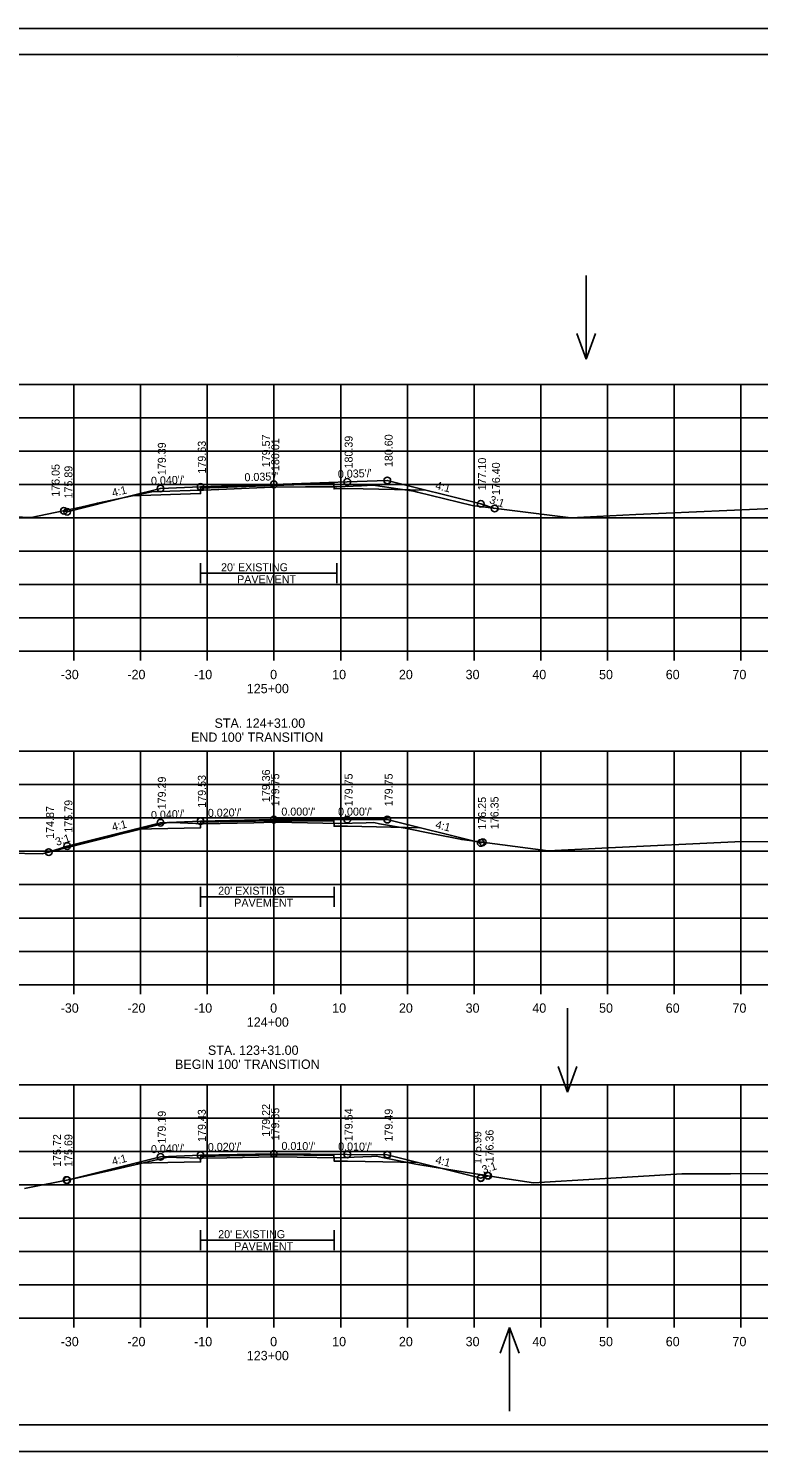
# Model space of a CAD drawing. Extents: x 915787 to 919910, y 133456 to 136717.
# Drawn here: x 916377.2 to 916486.6, y 136229.4 to 136442.8 of the extents above; entities that cross this region are included whole.
import ezdxf

# ---------------------------------------------------------------- set-up
doc = ezdxf.new("R2010")
doc.units = 0
for name, color, linetype in [('R_Axis', 7, 'Continuous'), ('R_Axis Annot', 7, 'Continuous'), ('R_Border', 7, 'Continuous'), ('R_Border Notes', 7, 'Continuous'), ('R_Exist Surface', 7, 'Continuous'), ('R_Exist Surface Annot', 7, 'Continuous'), ('R_Fin Surface', 7, 'Continuous'), ('R_Grid', 7, 'Continuous'), ('R_No Plot', 7, 'Continuous'), ('R_Water Annot', 7, 'Continuous'), ('R_Xsect Elev', 7, 'Continuous'), ('R_Xsect Slope', 7, 'Continuous')]:
    doc.layers.add(name, color=color, linetype=linetype)

msp = doc.modelspace()

# ---------------------------------------------------------------- linework, layer by layer
at = {"layer": 'R_Axis'}
for p, q in [((916273.98, 136349.41), (916553.98, 136349.41)), ((916383.98, 136348.01), (916383.98, 136349.41)), ((916393.98, 136348.01), (916393.98, 136349.41)), ((916403.98, 136348.01), (916403.98, 136349.41)), ((916413.98, 136348.01), (916413.98, 136349.41)), ((916423.98, 136348.01), (916423.98, 136349.41)), ((916433.98, 136348.01), (916433.98, 136349.41)), ((916443.98, 136348.01), (916443.98, 136349.41)), ((916453.98, 136348.01), (916453.98, 136349.41)), ((916463.98, 136348.01), (916463.98, 136349.41)), ((916473.98, 136348.01), (916473.98, 136349.41)), ((916483.98, 136348.01), (916483.98, 136349.41)), ((916273.98, 136299.41), (916553.98, 136299.41)), ((916383.98, 136298.01), (916383.98, 136299.41)), ((916393.98, 136298.01), (916393.98, 136299.41)), ((916403.98, 136298.01), (916403.98, 136299.41)), ((916413.98, 136298.01), (916413.98, 136299.41)), ((916423.98, 136298.01), (916423.98, 136299.41)), ((916433.98, 136298.01), (916433.98, 136299.41)), ((916443.98, 136298.01), (916443.98, 136299.41)), ((916453.98, 136298.01), (916453.98, 136299.41)), ((916463.98, 136298.01), (916463.98, 136299.41)), ((916473.98, 136298.01), (916473.98, 136299.41)), ((916483.98, 136298.01), (916483.98, 136299.41)), ((916273.98, 136249.41), (916553.98, 136249.41)), ((916383.98, 136248.01), (916383.98, 136249.41)), ((916393.98, 136248.01), (916393.98, 136249.41)), ((916403.98, 136248.01), (916403.98, 136249.41)), ((916413.98, 136248.01), (916413.98, 136249.41)), ((916423.98, 136248.01), (916423.98, 136249.41)), ((916433.98, 136248.01), (916433.98, 136249.41)), ((916443.98, 136248.01), (916443.98, 136249.41)), ((916453.98, 136248.01), (916453.98, 136249.41)), ((916463.98, 136248.01), (916463.98, 136249.41)), ((916473.98, 136248.01), (916473.98, 136249.41)), ((916483.98, 136248.01), (916483.98, 136249.41))]:
    msp.add_line(p, q, dxfattribs=at)
at = {"layer": 'R_Border'}
for p, q in [((916255.98, 136438.87), (916572.16, 136438.87)), ((916408.5, 136438.61), (916408.5, 136438.61)), ((916408.5, 136438.61), (916408.5, 136438.61)), ((916572.16, 136233.41), (916255.98, 136233.41))]:
    msp.add_line(p, q, dxfattribs=at)
at = {"layer": 'R_Exist Surface'}
for points in [[(916367.17, 136369.83), (916377.58, 136369.43), (916385.03, 136371), (916387.51, 136371.62), (916394.69, 136373.08), (916395.67, 136373.29), (916396.84, 136373.33), (916402.95, 136373.54), (916403.4, 136373.56), (916413.72, 136373.98), (916418.73, 136374.03), (916423.4, 136374.03), (916427.12, 136374.2), (916428.83, 136374.3), (916434.26, 136373.48), (916434.95, 136373.38), (916435.5, 136373.25), (916443.69, 136371.25), (916446.48, 136370.88), (916458.49, 136369.38), (916468.2, 136369.88), (916490.97, 136370.92)], [(916374.01, 136319.15), (916379.22, 136319.03), (916389.03, 136321.49), (916390.35, 136321.83), (916393.19, 136322.53), (916398.06, 136323.73), (916399.94, 136323.68), (916403.42, 136323.55), (916410.95, 136323.7), (916413.94, 136323.77), (916416.64, 136323.72), (916423.64, 136323.57), (916427.79, 136323.68), (916428.93, 136323.71), (916429.82, 136323.55), (916433.66, 136322.88), (916437.82, 136322.02), (916442.12, 136321.17), (916450.11, 136320.13), (916455.09, 136319.5), (916464.13, 136319.93), (916483.04, 136320.82), (916497.05, 136320.95)], [(916376.61, 136268.88), (916384.15, 136270.37), (916389.69, 136271.63), (916397.24, 136273.35), (916398.13, 136273.55), (916399.38, 136273.52), (916403.34, 136273.39), (916406.91, 136273.48), (916414.02, 136273.63), (916417.48, 136273.56), (916423.39, 136273.45), (916428.6, 136273.67), (916429.37, 136273.7), (916430.24, 136273.53), (916435.25, 136272.5), (916438.01, 136272.06), (916442.65, 136271.32), (916449.26, 136270.27), (916452.86, 136269.69), (916462.83, 136270.29), (916475.12, 136271.05), (916482.4, 136271.05), (916495.78, 136271.09)]]:
    msp.add_lwpolyline(points, dxfattribs=at)
at = {"layer": 'R_Exist Surface Annot'}
for p, q in [((916402.95, 136362.59), (916402.95, 136359.59)), ((916423.4, 136362.59), (916423.4, 136359.59)), ((916402.95, 136361.09), (916423.4, 136361.09)), ((916402.98, 136314.1), (916402.98, 136311.1)), ((916402.98, 136312.6), (916422.98, 136312.6)), ((916422.98, 136314.1), (916422.98, 136311.1)), ((916402.98, 136262.61), (916402.98, 136259.61)), ((916402.98, 136261.11), (916422.98, 136261.11)), ((916422.98, 136262.61), (916422.98, 136259.61))]:
    msp.add_line(p, q, dxfattribs=at)
at = {"layer": 'R_Fin Surface'}
for points in [[(916382.9, 136270.13), (916382.97, 136270.1), (916393.16, 136272.65), (916396.97, 136273.6), (916402.97, 136273.84), (916413.97, 136274.06), (916424.97, 136273.95), (916430.97, 136273.9), (916444.97, 136270.4), (916446.09, 136270.77)], [(916393.16, 136272.65), (916402.98, 136272.84), (916402.97, 136273.67), (916413.97, 136273.89), (916422.97, 136273.81), (916422.98, 136272.97), (916424.98, 136272.95), (916435.59, 136272.74)]]:
    msp.add_lwpolyline(points, dxfattribs=at)
at = {"layer": 'R_Grid'}
for p, q in [((916273.98, 136389.41), (916553.98, 136389.41)), ((916383.98, 136349.41), (916383.98, 136389.41)), ((916393.98, 136349.41), (916393.98, 136389.41)), ((916403.98, 136349.41), (916403.98, 136389.41)), ((916413.98, 136349.41), (916413.98, 136389.41)), ((916423.98, 136349.41), (916423.98, 136389.41)), ((916433.98, 136349.41), (916433.98, 136389.41)), ((916443.98, 136349.41), (916443.98, 136389.41)), ((916453.98, 136349.41), (916453.98, 136389.41)), ((916463.98, 136349.41), (916463.98, 136389.41)), ((916473.98, 136349.41), (916473.98, 136389.41)), ((916483.98, 136349.41), (916483.98, 136389.41)), ((916273.98, 136384.41), (916553.98, 136384.41)), ((916273.98, 136379.41), (916553.98, 136379.41)), ((916273.98, 136374.41), (916553.98, 136374.41)), ((916273.98, 136369.41), (916553.98, 136369.41)), ((916273.98, 136364.41), (916553.98, 136364.41)), ((916273.98, 136359.41), (916553.98, 136359.41)), ((916273.98, 136354.41), (916553.98, 136354.41)), ((916273.98, 136349.41), (916553.98, 136349.41)), ((916273.98, 136334.41), (916553.98, 136334.41)), ((916383.98, 136299.41), (916383.98, 136334.41)), ((916393.98, 136299.41), (916393.98, 136334.41)), ((916403.98, 136299.41), (916403.98, 136334.41)), ((916413.98, 136299.41), (916413.98, 136334.41)), ((916423.98, 136299.41), (916423.98, 136334.41)), ((916433.98, 136299.41), (916433.98, 136334.41)), ((916443.98, 136299.41), (916443.98, 136334.41)), ((916453.98, 136299.41), (916453.98, 136334.41)), ((916463.98, 136299.41), (916463.98, 136334.41)), ((916473.98, 136299.41), (916473.98, 136334.41)), ((916483.98, 136299.41), (916483.98, 136334.41)), ((916273.98, 136329.41), (916553.98, 136329.41)), ((916273.98, 136324.41), (916553.98, 136324.41)), ((916273.98, 136319.41), (916553.98, 136319.41)), ((916273.98, 136314.41), (916553.98, 136314.41)), ((916273.98, 136309.41), (916553.98, 136309.41)), ((916273.98, 136304.41), (916553.98, 136304.41)), ((916273.98, 136299.41), (916553.98, 136299.41)), ((916273.98, 136284.41), (916553.98, 136284.41)), ((916383.98, 136249.41), (916383.98, 136284.41)), ((916393.98, 136249.41), (916393.98, 136284.41)), ((916403.98, 136249.41), (916403.98, 136284.41)), ((916413.98, 136249.41), (916413.98, 136284.41)), ((916423.98, 136249.41), (916423.98, 136284.41)), ((916433.98, 136249.41), (916433.98, 136284.41)), ((916443.98, 136249.41), (916443.98, 136284.41)), ((916453.98, 136249.41), (916453.98, 136284.41)), ((916463.98, 136249.41), (916463.98, 136284.41)), ((916473.98, 136249.41), (916473.98, 136284.41)), ((916483.98, 136249.41), (916483.98, 136284.41)), ((916273.98, 136279.41), (916553.98, 136279.41)), ((916273.98, 136274.41), (916553.98, 136274.41)), ((916273.98, 136269.41), (916553.98, 136269.41)), ((916273.98, 136264.41), (916553.98, 136264.41)), ((916273.98, 136259.41), (916553.98, 136259.41)), ((916273.98, 136254.41), (916553.98, 136254.41)), ((916273.98, 136249.41), (916553.98, 136249.41))]:
    msp.add_line(p, q, dxfattribs=at)
at = {"layer": 'R_No Plot'}
for p, q in [((916243.57, 136442.76), (916576.91, 136442.76)), ((916243.57, 136229.43), (916576.91, 136229.43))]:
    msp.add_line(p, q, dxfattribs=at)
for points in [[(916243.57, 136442.76), (916576.91, 136442.76), (916576.91, 136229.43), (916243.57, 136229.43)], [(916489.9, 136438.87), (916489.9, 136428.99), (916525.63, 136428.99), (916525.63, 136426.07), (916548.83, 136426.07), (916548.83, 136402.85), (916572.16, 136402.85), (916572.16, 136233.41), (916255.98, 136233.41), (916255.98, 136438.87)]]:
    msp.add_lwpolyline(points, close=True, dxfattribs=at)
for points in [[(916382.48, 136370.46), (916382.97, 136370.3), (916392.5, 136372.68), (916396.97, 136373.8), (916402.97, 136374.04), (916413.97, 136374.42), (916424.97, 136374.8), (916430.97, 136375.01), (916444.97, 136371.51), (916447.06, 136370.81)], [(916392.5, 136372.68), (916402.98, 136373.04), (916402.97, 136373.87), (916413.97, 136374.25), (916422.97, 136374.56), (916422.98, 136373.73), (916424.98, 136373.8), (916436.74, 136373.56)], [(916380.21, 136319.28), (916382.97, 136320.2), (916393.16, 136322.75), (916396.97, 136323.7), (916402.97, 136323.94), (916413.97, 136324.16), (916424.97, 136324.16), (916430.97, 136324.16), (916444.97, 136320.66), (916445.27, 136320.76)], [(916393.16, 136322.75), (916402.98, 136322.94), (916402.97, 136323.77), (916413.97, 136323.99), (916422.97, 136323.99), (916422.98, 136323.16), (916424.98, 136323.16), (916435.85, 136322.94)]]:
    msp.add_lwpolyline(points, dxfattribs=at)
for centre in [(916396.97, 136373.8), (916396.97, 136373.8), (916402.97, 136374.04), (916402.97, 136374.04), (916413.97, 136374.42), (916413.97, 136374.42), (916424.97, 136374.8), (916424.97, 136374.8), (916430.97, 136375.01), (916430.97, 136375.01), (916444.97, 136371.51), (916444.97, 136371.51), (916382.48, 136370.46), (916382.48, 136370.46), (916382.97, 136370.3), (916382.97, 136370.3), (916447.06, 136370.81), (916447.06, 136370.81), (916396.97, 136323.7), (916396.97, 136323.7), (916402.97, 136323.94), (916402.97, 136323.94), (916413.97, 136324.16), (916413.97, 136324.16), (916424.97, 136324.16), (916424.97, 136324.16), (916430.97, 136324.16), (916430.97, 136324.16), (916382.97, 136320.2), (916382.97, 136320.2), (916444.97, 136320.66), (916444.97, 136320.66), (916445.27, 136320.76), (916445.27, 136320.76), (916445.27, 136320.76), (916445.27, 136320.76), (916380.21, 136319.28), (916380.21, 136319.28), (916396.97, 136273.6), (916396.97, 136273.6), (916402.97, 136273.84), (916402.97, 136273.84), (916413.97, 136274.06), (916413.97, 136274.06), (916424.97, 136273.99), (916424.97, 136273.95), (916430.97, 136273.95), (916430.97, 136273.9), (916382.9, 136270.13), (916382.9, 136270.13), (916382.9, 136270.13), (916382.9, 136270.13), (916382.97, 136270.1), (916382.97, 136270.1), (916444.97, 136270.45), (916444.97, 136270.4), (916445.98, 136270.79), (916446.09, 136270.77)]:
    msp.add_circle(centre, 0.5, dxfattribs=at)
at = {"layer": 'R_Water Annot'}
for p, q in [((916460.78, 136405.75), (916460.78, 136393.18)), ((916460.78, 136393.18), (916459.38, 136397.03)), ((916460.78, 136393.18), (916462.18, 136397.03)), ((916457.98, 136295.89), (916457.98, 136283.32)), ((916457.98, 136283.32), (916456.58, 136287.17)), ((916457.98, 136283.32), (916459.38, 136287.17)), ((916449.31, 136248.04), (916447.91, 136244.19)), ((916449.31, 136235.47), (916449.31, 136248.04)), ((916449.31, 136248.04), (916450.71, 136244.19))]:
    msp.add_line(p, q, dxfattribs=at)

# ---------------------------------------------------------------- texts
at = {"layer": 'R_Axis Annot'}
for s, p in [('-30', (916382.01, 136345.21)), ('-20', (916392.01, 136345.21)), ('-10', (916402.01, 136345.21)), ('0', (916413.41, 136345.21)), ('10', (916422.71, 136345.21)), ('20', (916432.71, 136345.21)), ('30', (916442.71, 136345.21)), ('40', (916452.71, 136345.21)), ('50', (916462.71, 136345.21)), ('60', (916472.71, 136345.21)), ('70', (916482.71, 136345.21)), ('125+00', (916409.91, 136343.11)), ('-30', (916382.01, 136295.21)), ('-20', (916392.01, 136295.21)), ('-10', (916402.01, 136295.21)), ('0', (916413.41, 136295.21)), ('10', (916422.71, 136295.21)), ('20', (916432.71, 136295.21)), ('30', (916442.71, 136295.21)), ('40', (916452.71, 136295.21)), ('50', (916462.71, 136295.21)), ('60', (916472.71, 136295.21)), ('70', (916482.71, 136295.21)), ('124+00', (916409.91, 136293.11)), ('-30', (916382.01, 136245.21)), ('-20', (916392.01, 136245.21)), ('-10', (916402.01, 136245.21)), ('0', (916413.41, 136245.21)), ('10', (916422.71, 136245.21)), ('20', (916432.71, 136245.21)), ('30', (916442.71, 136245.21)), ('40', (916452.71, 136245.21)), ('50', (916462.71, 136245.21)), ('60', (916472.71, 136245.21)), ('70', (916482.71, 136245.21)), ('123+00', (916409.91, 136243.11))]:
    msp.add_text(s, height=1.4, dxfattribs=at).set_placement(p)
at = {"layer": 'R_Border Notes'}
for s, p in [('STA. 124+31.00', (916405.07, 136337.92)), ("END 100' TRANSITION", (916401.55, 136335.82)), ('STA. 123+31.00', (916404.08, 136288.89)), ("BEGIN 100' TRANSITION", (916399.15, 136286.79))]:
    msp.add_text(s, height=1.4, dxfattribs=at).set_placement(p)
at = {"layer": 'R_Exist Surface Annot'}
for s, p in [("20' EXISTING", (916406.05, 136361.39)), ('PAVEMENT', (916408.46, 136359.59)), ("20' EXISTING", (916405.62, 136312.9)), ('PAVEMENT', (916408.03, 136311.1)), ("20' EXISTING", (916405.62, 136261.41)), ('PAVEMENT', (916408.03, 136259.61))]:
    msp.add_text(s, height=1.2, dxfattribs=at).set_placement(p)
at = {"layer": 'R_No Plot'}
for s, rotation, p in [('179.39', 90, (916397.77, 136375.8)), ('179.63', 90, (916403.77, 136376.04)), ('179.57', 90, (916413.38, 136376.98)), ('180.01', 90, (916414.77, 136376.42)), ('180.39', 90, (916425.77, 136376.8)), ('180.60', 90, (916431.77, 136377.01)), ('177.10', 90, (916445.77, 136373.51)), ('176.05', 90, (916381.85, 136372.56)), ('175.89', 90, (916383.77, 136372.3)), ("0.035'/'", 1.9768, (916409.58, 136374.87)), ("0.035'/'", 1.9768, (916423.58, 136375.35)), ('176.40', 90, (916447.86, 136372.81)), ('4:1', 14.0362, (916389.85, 136372.53)), ("0.040'/'", 2.2906, (916395.57, 136374.34)), ('4:1', 345.9638, (916438.1, 136373.74)), ('3:1', 341.5651, (916446.18, 136371.63)), ('179.36', 90, (916413.38, 136326.77)), ('179.29', 90, (916397.77, 136325.7)), ('179.53', 90, (916403.77, 136325.94)), ('179.75', 90, (916414.77, 136326.16)), ('179.75', 90, (916425.77, 136326.16)), ('179.75', 90, (916431.77, 136326.16)), ('175.79', 90, (916383.77, 136322.2)), ('176.25', 90, (916445.77, 136322.66)), ('176.35', 90, (916447.64, 136322.72)), ('174.87', 90, (916381.01, 136321.28)), ("0.040'/'", 2.2906, (916395.57, 136324.24)), ("0.020'/'", 1.1458, (916404.08, 136324.56)), ("0.000'/'", 0.0132, (916415.09, 136324.76)), ("0.000'/'", 0.0132, (916423.59, 136324.76)), ('4:1', 14.0362, (916389.85, 136322.43)), ('4:1', 345.9638, (916438.1, 136322.9)), ('3:1', 18.4349, (916381.44, 136320.21))]:
    msp.add_text(s, height=1.2, rotation=rotation, dxfattribs=at).set_placement(p)
at = {"layer": 'R_Xsect Elev'}
for s, p in [('179.19', (916397.77, 136275.6)), ('179.43', (916403.77, 136275.84)), ('179.22', (916413.38, 136276.63)), ('179.65', (916414.77, 136276.06)), ('179.54', (916425.77, 136275.95)), ('179.49', (916431.77, 136275.9)), ('175.72', (916382.06, 136272.1)), ('175.69', (916383.77, 136272.1)), ('175.99', (916445.07, 136272.53)), ('176.36', (916446.89, 136272.77))]:
    msp.add_text(s, height=1.2, rotation=90, dxfattribs=at).set_placement(p)
at = {"layer": 'R_Xsect Slope'}
for s, rotation, p in [("0.020'/'", 1.1458, (916404.08, 136274.46)), ("0.010'/'", 359.4527, (916415.1, 136274.65)), ('4:1', 14.0362, (916389.85, 136272.33)), ("0.040'/'", 2.2906, (916395.57, 136274.14)), ("0.010'/'", 359.4527, (916423.6, 136274.57)), ('4:1', 345.9638, (916438.1, 136272.63)), ('3:1', 18.4349, (916445.38, 136271.06))]:
    msp.add_text(s, height=1.2, rotation=rotation, dxfattribs=at).set_placement(p)

doc.saveas('drawing.dxf')
